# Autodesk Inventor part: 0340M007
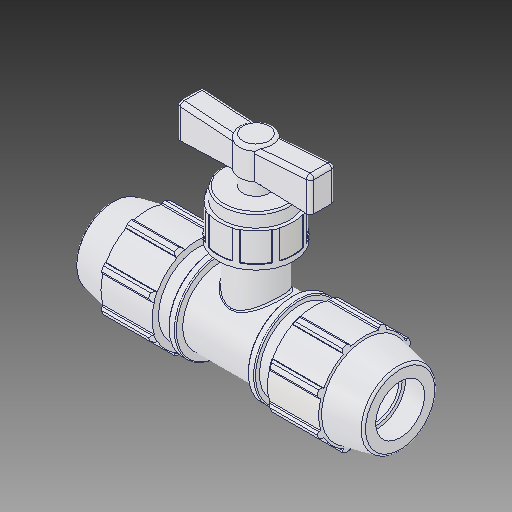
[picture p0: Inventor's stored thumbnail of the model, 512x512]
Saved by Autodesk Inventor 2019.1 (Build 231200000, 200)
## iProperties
Created: 2017-02
Part Number: 0340M007
Material: PVC-Piping
Description: PLASSON COMPRESSION STOPTAP 3/4'' - 3/4''
Document SubType Name: Modeling
Designer: KIM
Mass: 92.6774 g
Surface Area: 199.44 cm^2
Volume: 66.1981 cm^3
Density: 1.4 g/cm^3
Appearance: PTFE
Author: KIM
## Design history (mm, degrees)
derived "0340M0.ipt"
feature "Solid1::0340M0.ipt"
tag "TaggingFeature1"
body "Solid1"
other parameters: "d1" = 156.972, "d2" = 26.6, "d4" = 13.081, "d5" = 18.83664, "d7" = 54.102, "d8" = 40.5765, "d9" = 39.243, "d11" = 3.9243, "d12" = 43.2816, "d13" = 120 deg, "d14" = 39.9, "d15" = 12 deg, "d16" = 48.6918, "d18" = 1.33, "d19" = 35 deg, "d20" = 17.5 deg, "d21" = 50.31486, "d23" = 0, "d25" = 360 deg, "d27" = 1.08204, "d33" = 0.532, "d42" = 28.25496, "d43" = 1.62306, "d46" = 0.798, "d49" = 59.944, "d50" = 21.28, "d51" = 90.932, "d53" = 18.1864, "d54" = 18.1864, "d57" = 16.36776, "d60" = 40.9194, "d61" = 27.2796, "d62" = 18.1864, "d63" = 59.1058, "d64" = 14.54912, "d65" = 36.3728, "d66" = 7.27456, "d69" = 12.27582, "d70" = 6.13791, "d71" = 40.10101, "d72" = 41.4, "d74" = 0, "d75" = 15.45844, "d76" = 92, "d77" = 92, "d80" = 360 deg, "d82" = 0.36373, "d85" = 36.3728, "d86" = 6 deg, "d87" = 94 deg, "d88" = 13.6398, "d89" = 0, "d90" = 2, "d91" = 2, "d92" = 0.90932, "d93" = 0.90932, "d_" = 26.6, "E_" = 54.102, "H_" = 156.972, "l_" = 59.944, "A_" = 90.932, "d67" = 92, "d78" = 40.9194
